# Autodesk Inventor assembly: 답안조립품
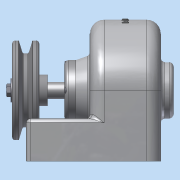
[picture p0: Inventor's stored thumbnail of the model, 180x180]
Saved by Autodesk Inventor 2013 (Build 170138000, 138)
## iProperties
Created: 2015-02
Part Number: 답안조립품
Document SubType Name: Assembly
Designer: Administrator
Author: Administrator
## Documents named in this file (14)
- C:\Documents and Settings\Administrator\바탕 화면\450214V1013\답안조립품.iam
- C:\Documents and Settings\Administrator\바탕 화면\450214V1013\1-본체.ipt
- C:\Documents and Settings\Administrator\바탕 화면\450214V1013\베어링 6001.ipt
- C:\Documents and Settings\Administrator\바탕 화면\450214V1013\축.ipt
- C:\Documents and Settings\Administrator\바탕 화면\450214V1013\키5x5.ipt
- C:\Documents and Settings\Administrator\바탕 화면\450214V1013\5-스퍼기어.ipt
- C:\Documents and Settings\Administrator\바탕 화면\450214V1013\축커버.ipt
- C:\Documents and Settings\Administrator\바탕 화면\450214V1013\오일실.ipt
- C:\Documents and Settings\Administrator\바탕 화면\450214V1013\M3x0.5.ipt
- C:\Documents and Settings\Administrator\바탕 화면\450214V1013\키4x4.ipt
- C:\Documents and Settings\Administrator\바탕 화면\450214V1013\4-V-벨트풀리.ipt
- C:\Documents and Settings\Administrator\바탕 화면\450214V1013\와샤.ipt
- C:\Documents and Settings\Administrator\바탕 화면\450214V1013\M5x0.8.ipt
- M5x0.8.ipt
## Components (7 placed, 4 different names)
1. 1-본체:1
2. 4-V-벨트풀리:1 — 각도:4
3. M5x0.8:1 — 각도:5, 각도:6
4. M3x0.5:1
5. M3x0.5:2
6. M3x0.5:3
7. M3x0.5:4
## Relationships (3: Angle 3)
- 각도:4 [Angle]: 4-V-벨트풀리:1
- 각도:5 [Angle]: M5x0.8:1
- 각도:6 [Angle]: M5x0.8:1
